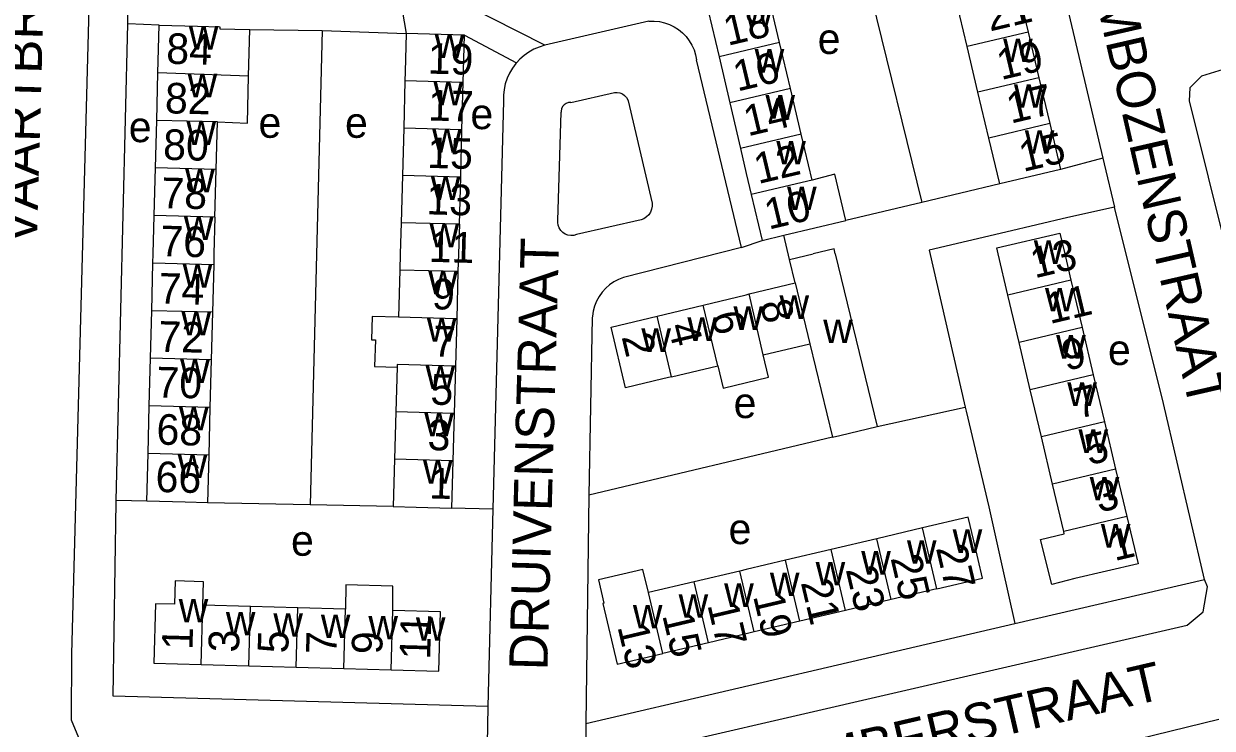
# Model space of a CAD drawing. Extents: x 161936 to 163647, y 386450 to 388633.
# Drawn here: x 162905.7 to 163060.8, y 387938 to 388030 of the extents above; entities that cross this region are included whole.
import ezdxf

# ---------------------------------------------------------------- set-up
doc = ezdxf.new("R2010")
doc.units = 0
for name, color, linetype in [('BLT_Basislijn', 7, 'Continuous'), ('BLT_Bebouwing', 7, 'Continuous'), ('BLT_Centroide', 7, 'Continuous'), ('BLT_Huisnummer', 7, 'Continuous'), ('BLT_Huisnummer_ tussenligend', 7, 'Continuous'), ('BLT_Onderverdeling_panden', 7, 'Continuous'), ('BLT_Straatnaam', 7, 'Continuous')]:
    doc.layers.add(name, color=color, linetype=linetype)

msp = doc.modelspace()

# ---------------------------------------------------------------- linework, layer by layer
at = {"layer": 'BLT_Basislijn'}
for p, q in [((163014.06, 388042.72), (163022.9, 388006.7)), ((162973.69, 388027.22), (162963.28, 388032.53)), ((162987.29, 388030.37), (162973.69, 388027.22)), ((162917.75, 387967.78), (162919.24, 388030.03)), ((162923.34, 388029.85), (162919.24, 388030.03)), ((162935.18, 388029.28), (162944.63, 388029.15)), ((162944.63, 388029.15), (162943.04, 387967.21)), ((162944.63, 388029.15), (162955.61, 388028.75)), ((162963.22, 388028.54), (162969.99, 388024.93)), ((162999.39, 388000.82), (162993.49, 388025.34)), ((162977.08, 388019.77), (162982.81, 388021.04)), ((162968.3, 388019.98), (162966.91, 387966.63)), ((162984.57, 388019.99), (162987.71, 388006.62)), ((162975.38, 388004.32), (162975.83, 388018.48)), ((163046.55, 388012.49), (163041.04, 388011.02)), ((163033.08, 388009.13), (163022.9, 388006.7)), ((163022.9, 388006.7), (163012.99, 388004.32)), ((162986.26, 388004.41), (162977.85, 388002.49)), ((163005.66, 387999.26), (163004.92, 388002.42)), ((162999.39, 388000.82), (163002.06, 388001.74)), ((162999.39, 388000.82), (162983.97, 387996.89)), ((162979.88, 387991.61), (162979.42, 387968.45)), ((163017.08, 387977.43), (163028.59, 387979.96)), ((163011.25, 387976.02), (162979.42, 387968.45)), ((162979.42, 387968.45), (162979.05, 387938.62)), ((162921.72, 387967.68), (162917.75, 387967.78)), ((162943.04, 387967.21), (162929.66, 387967.48)), ((162953.9, 387966.99), (162943.04, 387967.21)), ((162966.91, 387966.63), (162961.51, 387966.78)), ((162966.91, 387966.63), (162966.26, 387940.86)), ((163035.08, 387951.7), (163059.84, 387957.46)), ((162979.05, 387938.62), (163035.08, 387951.7)), ((162966.26, 387940.86), (162966.15, 387935.92))]:
    msp.add_line(p, q, dxfattribs=at)
for points in [[(163027.43, 388091.6), (163030.62, 388079.99), (163046.55, 388012.49)], [(162920.52, 388086.96), (162917.09, 388086.07), (162915.57, 388084.03), (162911.89, 387947.72), (162911.87, 387939.13), (162913.45, 387935.24), (162916.88, 387931.65)], [(162919.24, 388030.03), (162919.25, 388030.56), (162920.34, 388074.07), (162947.85, 388074), (162955.61, 388028.75)], [(162987.29, 388030.37), (162987.98, 388030.39), (162988.65, 388030.32), (162989.32, 388030.17), (162989.96, 388029.95), (162990.57, 388029.65), (162991.15, 388029.29), (162991.67, 388028.85), (162992.14, 388028.36), (162992.56, 388027.82), (162992.9, 388027.24), (162993.18, 388026.61), (162993.37, 388025.96), (162993.49, 388025.34)], [(163085.18, 388029.19), (163062.27, 388024.08), (163059.42, 388023.18), (163057.92, 388021.66), (163057.84, 388019.99), (163067.73, 387980.1)], [(162973.69, 388027.22), (162972.97, 388027), (162972.28, 388026.7), (162971.62, 388026.34), (162971, 388025.9), (162970.43, 388025.4), (162969.99, 388024.93)], [(162969.99, 388024.93), (162969.92, 388024.85), (162969.47, 388024.24), (162969.08, 388023.6), (162968.77, 388022.91), (162968.53, 388022.19), (162968.37, 388021.46), (162968.28, 388020.71), (162968.3, 388019.98)], [(162982.81, 388021.04), (162983.16, 388021.07), (162983.51, 388021.01), (162983.84, 388020.88), (162984.12, 388020.68), (162984.36, 388020.41), (162984.53, 388020.1), (162984.57, 388019.99)], [(162977.08, 388019.77), (162976.77, 388019.74), (162976.48, 388019.63), (162976.22, 388019.45), (162976.02, 388019.22), (162975.89, 388018.93), (162975.83, 388018.63), (162975.83, 388018.48)], [(163046.55, 388012.49), (163046.73, 388011.76), (163048.06, 388006.06)], [(162987.71, 388006.62), (162987.71, 388006.21), (162987.64, 388005.81), (162987.48, 388005.43), (162987.26, 388005.09), (162986.97, 388004.8), (162986.63, 388004.57), (162986.26, 388004.41)], [(163048.06, 388006.06), (163041.98, 388004.71), (163033.89, 388002.81), (163023.89, 388000.48), (163028.59, 387979.96)], [(163059.84, 387957.46), (163054.49, 387980.45), (163048.06, 388006.06)], [(162977.85, 388002.49), (162977.48, 388002.39), (162977.1, 388002.37), (162976.72, 388002.43), (162976.37, 388002.56), (162976.05, 388002.77), (162975.78, 388003.04), (162975.57, 388003.36), (162975.44, 388003.71), (162975.38, 388004.09), (162975.38, 388004.32)], [(162983.97, 387996.89), (162983.33, 387996.64), (162982.72, 387996.32), (162982.15, 387995.93), (162981.64, 387995.48), (162981.18, 387994.97), (162980.78, 387994.41), (162980.44, 387993.81), (162980.18, 387993.17), (162980, 387992.51), (162979.9, 387991.83), (162979.88, 387991.61)], [(163028.59, 387979.96), (163028.71, 387979.43), (163031.66, 387966.95), (163033.4, 387959.12), (163035.08, 387951.7)], [(162966.26, 387940.86), (162917.33, 387942.22), (162917.74, 387967.53), (162917.75, 387967.78)], [(162979.05, 387938.62), (162979.02, 387933.46), (162980.7, 387933.7), (163057.56, 387951.49), (163059.66, 387953.24), (163060.23, 387956.49), (163059.84, 387957.46)], [(163061.68, 387939.16), (163036.26, 387932.93), (163035.37, 387931.05), (163038.11, 387918.5)]]:
    msp.add_lwpolyline(points, dxfattribs=at)
at = {"layer": 'BLT_Bebouwing'}
for p, q in [((163004.33, 388027.58), (163002.91, 388033.58)), ((163035.38, 388034.94), (163036.8, 388028.96)), ((163028.84, 388027.08), (163027.42, 388033.06)), ((162995.04, 388031.71), (162996.44, 388025.72)), ((162923.18, 388023.64), (162923.34, 388029.85)), ((162935.02, 388023.21), (162935.18, 388029.28)), ((163036.8, 388028.96), (163038.21, 388022.98)), ((162963.22, 388028.54), (162955.61, 388028.75)), ((162963.05, 388022.36), (162963.22, 388028.54)), ((163005.75, 388021.59), (163004.33, 388027.58)), ((162996.44, 388025.72), (162997.84, 388019.72)), ((163030.25, 388021.1), (163028.84, 388027.08)), ((162923.02, 388017.42), (162923.18, 388023.64)), ((162955.44, 388022.57), (162955.27, 388016.4)), ((163038.21, 388022.98), (163039.63, 388017)), ((162962.88, 388016.19), (162963.05, 388022.36)), ((163007.16, 388015.6), (163005.75, 388021.59)), ((163031.67, 388015.11), (163030.25, 388021.1)), ((162997.84, 388019.72), (162999.24, 388013.73)), ((162922.85, 388011.2), (162923.02, 388017.42)), ((162930.79, 388011), (162930.95, 388017.22)), ((162955.27, 388016.4), (162955.1, 388010.22)), ((163039.63, 388017), (163041.04, 388011.02)), ((162962.71, 388010.01), (162962.88, 388016.19)), ((163008.58, 388009.61), (163007.16, 388015.6)), ((163033.08, 388009.13), (163031.67, 388015.11)), ((162999.24, 388013.73), (163000, 388010.48)), ((162922.69, 388004.99), (162922.85, 388011.2)), ((162930.63, 388004.78), (162930.79, 388011)), ((162955.1, 388010.22), (162954.93, 388004.05)), ((163000, 388010.48), (163000.65, 388007.73)), ((163041.04, 388011.02), (163033.08, 388009.13)), ((162962.54, 388003.84), (162962.71, 388010.01)), ((163000.65, 388007.73), (163002.06, 388001.74)), ((163004.92, 388002.42), (163012.99, 388004.32)), ((163002.06, 388001.74), (163004.92, 388002.42)), ((163005.66, 387999.26), (163008.72, 388000)), ((163011.62, 388000), (163017.08, 387977.43)), ((163034.15, 387994.59), (163032.87, 388000)), ((163041.57, 388000), (163042.39, 387996.53)), ((162922.37, 387992.55), (162922.53, 387998.77)), ((162930.47, 387998.56), (162930.31, 387992.35)), ((162954.76, 387997.87), (162954.59, 387991.73)), ((163006.4, 387996.18), (163005.66, 387999.26)), ((162962.36, 387997.66), (162962.19, 387991.48)), ((163042.39, 387996.53), (163043.85, 387990.36)), ((163000.38, 387994.74), (163006.4, 387996.18)), ((162988.35, 387991.86), (162994.37, 387993.3)), ((163035.61, 387988.42), (163034.15, 387994.59)), ((162922.21, 387986.34), (162922.37, 387992.55)), ((162930.31, 387992.35), (162930.14, 387986.13)), ((162962.19, 387991.48), (162962.02, 387985.31)), ((163043.85, 387990.36), (163045.3, 387984.19)), ((163002.21, 387986.78), (163008.29, 387988.24)), ((163008.29, 387988.24), (163011.25, 387976.02)), ((163037.06, 387982.24), (163035.61, 387988.42)), ((162922.05, 387980.12), (162922.21, 387986.34)), ((162930.14, 387986.13), (162929.98, 387979.91)), ((162990.25, 387983.92), (162996.27, 387985.36)), ((162954.4, 387985.17), (162954.24, 387979.34)), ((162962.02, 387985.31), (162961.85, 387979.13)), ((163045.3, 387984.19), (163046.76, 387978.02)), ((163038.52, 387976.07), (163037.06, 387982.24)), ((162921.89, 387973.9), (162922.05, 387980.12)), ((162929.98, 387979.91), (162929.82, 387973.7)), ((162954.24, 387979.34), (162954.07, 387973.17)), ((162961.85, 387979.13), (162961.68, 387972.96)), ((163046.76, 387978.02), (163048.22, 387971.85)), ((163039.98, 387969.9), (163038.52, 387976.07)), ((162921.72, 387967.68), (162921.89, 387973.9)), ((162929.82, 387973.7), (162929.66, 387967.48)), ((162954.07, 387973.17), (162953.9, 387966.99)), ((162961.68, 387972.96), (162961.51, 387966.78)), ((163048.22, 387971.85), (163049.68, 387965.68)), ((163041.44, 387963.73), (163039.98, 387969.9)), ((163023.02, 387964.18), (163017.05, 387962.77)), ((163017.05, 387962.77), (163011.09, 387961.37)), ((163011.09, 387961.37), (163005.12, 387959.96)), ((162999.16, 387958.55), (162993.19, 387957.15)), ((162993.19, 387957.15), (162987.23, 387955.74)), ((163024.89, 387956.22), (163018.93, 387954.82)), ((163018.93, 387954.82), (163012.96, 387953.41)), ((162935.26, 387953.93), (162929.06, 387954.11)), ((162941.46, 387953.76), (162935.26, 387953.93)), ((162947.67, 387953.58), (162941.46, 387953.76)), ((163012.96, 387953.41), (163007, 387952)), ((163007, 387952), (163001.04, 387950.59)), ((162995.07, 387949.19), (162989.11, 387947.78)), ((162928.84, 387946.35), (162935.04, 387946.18)), ((162935.04, 387946.18), (162941.24, 387946)), ((162941.24, 387946), (162947.45, 387945.83)), ((162947.45, 387945.83), (162953.65, 387945.65))]:
    msp.add_line(p, q, dxfattribs=at)
for points in [[(162923.34, 388029.85), (162928.34, 388029.72), (162931.27, 388029.65), (162931.27, 388029.38), (162935.18, 388029.28)], [(162955.61, 388028.75), (162955.47, 388023.75), (162955.44, 388022.57)], [(162930.95, 388017.22), (162934.86, 388017.04), (162935.02, 388023.21)], [(163012.99, 388004.32), (163011.55, 388010.41), (163008.58, 388009.61)], [(162922.53, 387998.77), (162922.56, 388000), (162922.69, 388004.99)], [(162930.63, 388004.78), (162930.5, 388000), (162930.47, 387998.56)], [(162954.93, 388004.05), (162954.82, 388000), (162954.76, 387997.87)], [(162962.54, 388003.84), (162962.43, 388000), (162962.36, 387997.66)], [(163032.87, 388000), (163032.69, 388000.76), (163040.93, 388002.7), (163041.57, 388000)], [(163011.62, 388000), (163011.46, 388000.66), (163008.72, 388000)], [(162994.37, 387993.3), (163000, 387994.65), (163000.38, 387994.74)], [(162954.59, 387991.73), (162951.16, 387991.82), (162951.07, 387988.76), (162951.57, 387988.75), (162951.48, 387985.25), (162954.4, 387985.17)], [(162990.25, 387983.92), (162989.1, 387983.64), (162984.24, 387982.48), (162982.34, 387990.42), (162988.35, 387991.86)], [(162996.27, 387985.36), (162996.96, 387982.44), (163002.91, 387983.86), (163002.21, 387986.78)], [(163011.25, 387976.02), (163012.22, 387976.25), (163017.08, 387977.43)], [(162929.66, 387967.48), (162926.72, 387967.55), (162921.72, 387967.68)], [(162953.9, 387966.99), (162956.92, 387966.91), (162961.51, 387966.78)], [(163024.89, 387956.22), (163030.85, 387957.63), (163029.7, 387962.5), (163028.97, 387965.59), (163023.02, 387964.18)], [(163049.68, 387965.68), (163051.14, 387959.51), (163042.9, 387957.56), (163039.88, 387956.8), (163038.43, 387962.67), (163041.52, 387963.4), (163041.44, 387963.73)], [(163005.12, 387959.96), (163000, 387958.75), (162999.16, 387958.55)], [(162987.23, 387955.74), (162986.51, 387958.77), (162980.7, 387957.4), (162981.41, 387954.36), (162981.27, 387954.33), (162983.14, 387946.37), (162989.11, 387947.78)], [(162929.06, 387954.11), (162929.14, 387957.16), (162925.45, 387957.26), (162925.36, 387954.21)], [(162953.87, 387953.41), (162953.86, 387956.56), (162947.7, 387956.73), (162947.67, 387953.58)], [(162925.36, 387954.21), (162922.86, 387954.29), (162922.64, 387946.53), (162928.84, 387946.35)], [(162953.65, 387945.65), (162959.85, 387945.47), (162960.07, 387953.23), (162953.87, 387953.41)], [(163001.04, 387950.59), (163000, 387950.35), (162995.07, 387949.19)]]:
    msp.add_lwpolyline(points, dxfattribs=at)
at = {"layer": 'BLT_Onderverdeling_panden'}
for p, q in [((163036.8, 388028.96), (163028.84, 388027.08)), ((163004.33, 388027.58), (162996.44, 388025.72)), ((162935.02, 388023.21), (162923.18, 388023.64)), ((162963.05, 388022.36), (162955.44, 388022.57)), ((163038.21, 388022.98), (163030.25, 388021.1)), ((163005.75, 388021.59), (162997.84, 388019.72)), ((162930.95, 388017.22), (162923.02, 388017.42)), ((162962.88, 388016.19), (162955.27, 388016.4)), ((163039.63, 388017), (163031.67, 388015.11)), ((163007.16, 388015.6), (162999.24, 388013.73)), ((162930.79, 388011), (162922.85, 388011.2)), ((162962.71, 388010.01), (162955.1, 388010.22)), ((163008.58, 388009.61), (163000.65, 388007.73)), ((162930.63, 388004.78), (162922.69, 388004.99)), ((162962.54, 388003.84), (162954.93, 388004.05)), ((162930.47, 387998.56), (162922.53, 387998.77)), ((162962.36, 387997.66), (162954.76, 387997.87)), ((163042.39, 387996.53), (163034.15, 387994.59)), ((163002.21, 387986.78), (163000.38, 387994.74)), ((163006.4, 387996.18), (163008.29, 387988.24)), ((162996.27, 387985.36), (162994.37, 387993.3)), ((162930.31, 387992.35), (162922.37, 387992.55)), ((162962.19, 387991.48), (162954.59, 387991.73)), ((162990.25, 387983.92), (162988.35, 387991.86)), ((163043.85, 387990.36), (163035.61, 387988.42)), ((162930.14, 387986.13), (162922.21, 387986.34)), ((163045.3, 387984.19), (163037.06, 387982.24)), ((162929.98, 387979.91), (162922.05, 387980.12)), ((162961.85, 387979.13), (162954.24, 387979.34)), ((163046.76, 387978.02), (163038.52, 387976.07)), ((162929.82, 387973.7), (162921.89, 387973.9)), ((162961.68, 387972.96), (162954.07, 387973.17)), ((163048.22, 387971.85), (163039.98, 387969.9)), ((163049.68, 387965.68), (163041.44, 387963.73)), ((163024.89, 387956.22), (163023.02, 387964.18)), ((163018.93, 387954.82), (163017.05, 387962.77)), ((163012.96, 387953.41), (163011.09, 387961.37)), ((163007, 387952), (163005.12, 387959.96)), ((163001.04, 387950.59), (162999.16, 387958.55)), ((162995.07, 387949.19), (162993.19, 387957.15)), ((162989.11, 387947.78), (162987.23, 387955.74)), ((162928.84, 387946.35), (162929.06, 387954.11)), ((162935.04, 387946.18), (162935.26, 387953.93)), ((162941.24, 387946), (162941.46, 387953.76)), ((162947.45, 387945.83), (162947.67, 387953.58)), ((162953.65, 387945.65), (162953.87, 387953.41))]:
    msp.add_line(p, q, dxfattribs=at)
msp.add_lwpolyline([(162962.02, 387985.31), (162954.41, 387985.52), (162954.4, 387985.17)], dxfattribs=at)

# ---------------------------------------------------------------- texts
at = {"layer": 'BLT_Centroide'}
for s, p in [('w', (162999.68, 388029.66)), ('w', (162927.22, 388026.66)), ('e', (163009.32, 388026.09)), ('w', (162959.33, 388025.56)), ('w', (163033.53, 388025.03)), ('w', (163001.09, 388023.66)), ('w', (162927.06, 388020.44)), ('w', (162959.16, 388019.38)), ('w', (163034.94, 388019.06)), ('w', (163002.5, 388017.66)), ('e', (162936.32, 388015.14)), ('e', (162947.61, 388015.14)), ('e', (162963.98, 388016.27)), ('e', (162919.38, 388014.57)), ('w', (162926.91, 388014.22)), ('w', (162958.99, 388013.22)), ('w', (163036.36, 388013.06)), ('w', (163003.91, 388011.66)), ('w', (162926.74, 388008)), ('w', (162958.82, 388007.03)), ('w', (163005.32, 388005.69)), ('w', (162926.58, 388001.78)), ('w', (162958.65, 388000.84)), ('w', (163037.54, 387998.66)), ('w', (162926.42, 387995.56)), ('w', (162958.48, 387994.69)), ('w', (163038.99, 387992.47)), ('w', (162998.33, 387990.05)), ('w', (163004.33, 387991.48)), ('w', (162926.26, 387989.34)), ('w', (162958.3, 387988.5)), ('w', (162992.31, 387988.61)), ('w', (162986.3, 387987.17)), ('w', (163010.04, 387988.33)), ('w', (163040.45, 387986.31)), ('e', (163047.22, 387985.46)), ('w', (162926.09, 387983.12)), ('w', (162958.13, 387982.31)), ('w', (163041.91, 387980.12)), ('e', (162998.35, 387978.53)), ('w', (162925.94, 387976.91)), ('w', (162957.96, 387976.16)), ('w', (163043.37, 387973.97)), ('w', (162925.77, 387970.69)), ('w', (162957.79, 387969.97)), ('w', (163044.83, 387967.78)), ('e', (162997.69, 387962.07)), ('e', (162940.56, 387960.55)), ('w', (163026.94, 387960.91)), ('w', (163046.29, 387961.62)), ('w', (163020.97, 387959.5)), ('w', (163015, 387958.09)), ('w', (163009.05, 387956.67)), ('w', (163003.08, 387955.27)), ('w', (162997.11, 387953.86)), ('w', (162925.89, 387951.84)), ('w', (162991.16, 387952.45)), ('w', (162932.05, 387950.14)), ('w', (162938.25, 387949.97)), ('w', (162944.45, 387949.8)), ('w', (162985.19, 387951.05)), ('w', (162950.66, 387949.61)), ('w', (162956.86, 387949.44))]:
    msp.add_text(s, height=4, dxfattribs=at).set_placement(p)
at = {"layer": 'BLT_Huisnummer'}
for s, rotation, p in [('84', 358.5138, (162924.24, 388024.82)), ('19', 358.4126, (162958.37, 388023.53)), ('19', 13.3059, (163033.26, 388022.67)), ('14', 13.3107, (163000.2, 388015.32)), ('15', 13.3091, (163036.15, 388010.67)), ('78', 358.5138, (162923.61, 388005.97)), ('13', 358.412, (162958.19, 388005.15)), ('10', 13.304, (163002.92, 388003.13)), ('13', 13.2959, (163037.65, 387996.77)), ('74', 358.5134, (162923.24, 387993.49)), ('9', 358.4118, (162958.92, 387992.76)), ('8', 283.463, (163001.77, 387993.55)), ('2', 283.463, (162983.7, 387989.16)), ('9', 13.2959, (163041.74, 387984.68)), ('70', 358.5133, (162922.95, 387981.24)), ('5', 358.4116, (162958.72, 387980.3)), ('5', 13.2975, (163044.73, 387972.36)), ('66', 358.5103, (162922.84, 387968.89)), ('1', 358.4052, (162958.57, 387968.04)), ('1', 13.2975, (163048.08, 387959.84)), ('27', 283.2714, (163024.74, 387961.56)), ('21', 283.2714, (163007.1, 387957.06)), ('17', 283.2782, (162994.9, 387954.14)), ('11', 88.383, (162958.72, 387946.96)), ('13', 283.2714, (162983.16, 387951.29)), ('1', 88.3828, (162927.69, 387948.22)), ('5', 88.3752, (162940.19, 387947.76))]:
    msp.add_text(s, height=4, rotation=rotation, dxfattribs=at).set_placement(p)
at = {"layer": 'BLT_Huisnummer_ tussenligend'}
for s, rotation, p in [('21', 13.3059, (163031.81, 388029.02)), ('18', 13.3107, (162997.57, 388027.14)), ('16', 13.3107, (162998.83, 388021.17)), ('82', 358.5138, (162924.07, 388018.35)), ('17', 358.412, (162958.41, 388017.41)), ('17', 13.3091, (163034.53, 388016.98)), ('80', 358.5138, (162923.83, 388012.28)), ('15', 358.412, (162958.31, 388011.22)), ('12', 13.304, (163001.55, 388009.09)), ('76', 358.5134, (162923.47, 387999.68)), ('11', 358.4118, (162958.5, 387998.95)), ('11', 13.2959, (163039.62, 387990.8)), ('6', 283.463, (162995.39, 387992.04)), ('72', 358.5133, (162923.2, 387987.21)), ('7', 358.4116, (162959.05, 387986.6)), ('4', 283.463, (162989.77, 387990.55)), ('7', 13.2975, (163043.34, 387978.43)), ('68', 358.5103, (162922.96, 387975.08)), ('3', 358.4052, (162958.35, 387974.36)), ('3', 13.2975, (163046.04, 387966.16)), ('25', 283.2714, (163018.81, 387960.25)), ('23', 283.2714, (163012.96, 387958.76)), ('19', 283.2782, (163000.87, 387955.28)), ('15', 283.2714, (162989.01, 387952.78)), ('3', 88.3828, (162933.76, 387947.88)), ('7', 88.3752, (162946.5, 387947.63)), ('9', 88.3752, (162952.46, 387947.64))]:
    msp.add_text(s, height=4, rotation=rotation, dxfattribs=at).set_placement(p)
at = {"layer": 'BLT_Straatnaam'}
for s, rotation, p in [('VAARTBROEK', 88.3879, (162907.37, 388001.18)), ('FRAMBOZENSTRAAT', 282.9113, (163042.65, 388046.22)), ('DRUIVENSTRAAT', 88.4473, (162974.03, 387945.54)), ('GEMBERSTRAAT', 13.095, (163000.68, 387929.36))]:
    msp.add_text(s, height=5, rotation=rotation, dxfattribs=at).set_placement(p)

doc.saveas('drawing.dxf')
